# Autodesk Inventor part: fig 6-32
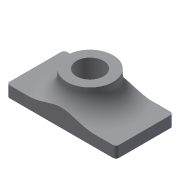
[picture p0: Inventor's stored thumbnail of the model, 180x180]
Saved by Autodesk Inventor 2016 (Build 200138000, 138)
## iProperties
Created: 2004-05
Part Number: fig 6-32
Document SubType Name: Modeling
Designer: CADCIM Technologies
Manufacturer: Standard
Standards Organization: Custom
Density: 1 g/cm^3
Material: Generic
Appearance: Default
Author: CADCIM Technologies
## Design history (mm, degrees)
sketch "Sketch1"
  geometry: L1 (-39.276, -18.692)-(33.721, -18.692); L2 (33.721, -18.692)-(33.721, 19.728); L3 (33.721, 19.728)-(-39.276, 19.728); L4 (-39.276, 19.728)-(-39.276, -18.692)
  constraints: 8 end point, 2 parallel, 1 horizontal, 1 perpendicular
extrude "Extrusion1" new body sketch "Sketch1" distance "d0" = 7.5; taper "d1" = 0 deg
fillet "Fillet1" dims "d2" = 2
sketch "Sketch2"
  geometry: C1 r 15.456 at (-2.778, 0.518)
  constraints: 1 centre point
extrude "Extrusion2" join sketch "Sketch2" distance "d3" = 17.25; taper "d4" = 0 deg
hole "Hole1" diameter "d8" = 18; stored, may be unused: countersink angle "d12" = 90 deg, drill point angle "d14" = 118 deg; dims "d6" = 10, "d7" = 10, "d9" = 6, "d10" = 4, "d11" = 2, "d13" = 8
fillet "Fillet2" dims "d5" = 14
body "Solid1"
